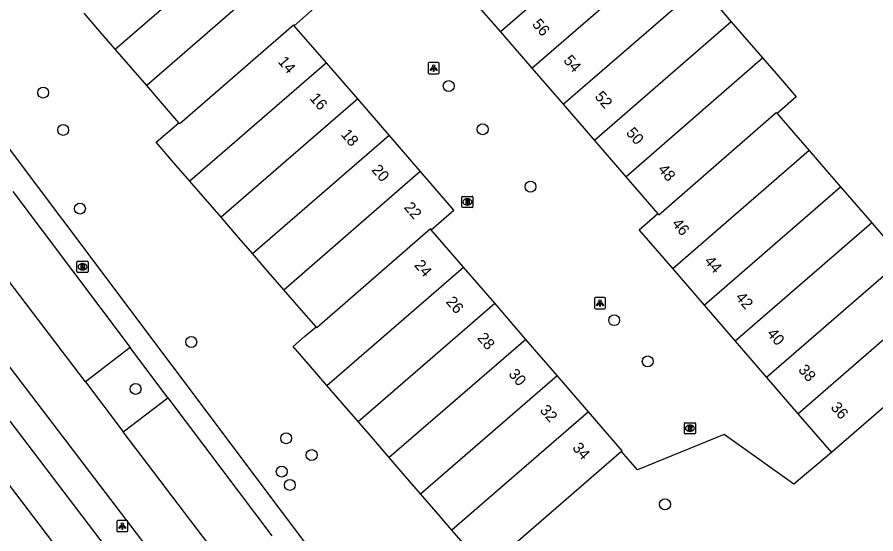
# Model space of a CAD drawing. Extents: x 156664 to 157568, y 383571 to 384421.
# Drawn here: x 156895.5 to 156972.4, y 384208.1 to 384254.3 of the extents above; entities that cross this region are included whole.
import ezdxf

# ---------------------------------------------------------------- set-up
doc = ezdxf.new("R2010")
doc.units = 0
for name, color, linetype in [('IMGEO_Boom', 7, 'Continuous'), ('IMGEO_Brandkraan', 7, 'Continuous'), ('IMGEO_Fietspad_gesloten', 7, 'Continuous'), ('IMGEO_Lichtpunt', 7, 'Continuous'), ('IMGEO_Muur', 7, 'Continuous'), ('IMGEO_Pand', 7, 'Continuous'), ('IMGEO_Pand_nummerreeks', 7, 'Continuous'), ('IMGEO_Parkeervlak_open', 7, 'Continuous'), ('IMGEO_Rijbaan_lokaal_gesloten', 7, 'Continuous'), ('IMGEO_Rioolput', 7, 'Continuous'), ('IMGEO_Voetpad_halfverhard', 7, 'Continuous'), ('IMGEO_Voetpad_open', 7, 'Continuous')]:
    doc.layers.add(name, color=color, linetype=linetype)

msp = doc.modelspace()

# ---------------------------------------------------------------- linework, layer by layer
at = {"layer": 'IMGEO_Boom'}
for centre in [(156934.175, 384248.153), (156897.869, 384247.575), (156899.659, 384244.232), (156937.213, 384244.294), (156941.494, 384239.152), (156901.161, 384237.192), (156948.982, 384227.205), (156911.121, 384225.255), (156951.985, 384223.521), (156906.138, 384221.057), (156919.623, 384216.642), (156921.906, 384215.136), (156919.227, 384213.661), (156919.951, 384212.466), (156953.531, 384210.728)]:
    msp.add_circle(centre, 0.489, dxfattribs=at)
at = {"layer": 'IMGEO_Brandkraan'}
for p, q in [((156935.344, 384237.363), (156935.344, 384238.215)), ((156935.419, 384238.289), (156936.271, 384238.289)), ((156935.832, 384238.069), (156935.857, 384238.069)), ((156936.345, 384238.215), (156936.345, 384237.363)), ((156936.271, 384237.289), (156935.419, 384237.289)), ((156935.855, 384237.509), (156935.83, 384237.509)), ((156900.895, 384231.56), (156900.895, 384232.412)), ((156900.97, 384232.486), (156901.822, 384232.486)), ((156901.383, 384232.266), (156901.408, 384232.266)), ((156901.896, 384232.412), (156901.896, 384231.56)), ((156901.822, 384231.486), (156900.97, 384231.486)), ((156901.406, 384231.706), (156901.381, 384231.706))]:
    msp.add_line(p, q, dxfattribs=at)
for points in [[(156935.344, 384237.363), (156935.344, 384238.215)], [(156935.419, 384238.289), (156936.271, 384238.289)], [(156935.692, 384237.989), (156935.692, 384237.589), (156935.905, 384237.589)], [(156935.923, 384237.989), (156935.692, 384237.989)], [(156935.871, 384237.908), (156935.817, 384237.908), (156935.817, 384237.832)], [(156935.817, 384237.832), (156935.87, 384237.832)], [(156935.879, 384237.756), (156935.817, 384237.756), (156935.817, 384237.675)], [(156935.817, 384237.675), (156935.879, 384237.675)], [(156936.345, 384238.215), (156936.345, 384237.363)], [(156936.271, 384237.289), (156935.419, 384237.289)], [(156900.895, 384231.56), (156900.895, 384232.412)], [(156900.97, 384232.486), (156901.822, 384232.486)], [(156901.243, 384232.186), (156901.243, 384231.786), (156901.456, 384231.786)], [(156901.474, 384232.186), (156901.243, 384232.186)], [(156901.896, 384232.412), (156901.896, 384231.56)], [(156901.822, 384231.486), (156900.97, 384231.486)], [(156901.422, 384232.105), (156901.368, 384232.105), (156901.368, 384232.029)], [(156901.368, 384232.029), (156901.421, 384232.029)], [(156901.43, 384231.953), (156901.368, 384231.953), (156901.368, 384231.872)], [(156901.368, 384231.872), (156901.43, 384231.872)]]:
    msp.add_lwpolyline(points, dxfattribs=at)
for centre, radius, start, end in [((156935.421, 384238.213), 0.0765, 91.55205, 178.44795), ((156935.421, 384238.213), 0.0765, 91.55205, 178.44795), ((156935.872, 384237.87), 0.0379, 267.82845, 90.93552), ((156935.88, 384237.715), 0.0404, 269.87594, 90.50774), ((156935.911, 384237.84), 0.251, 268.66757, 293.53466), ((156935.927, 384237.844), 0.145, 59.4692, 91.53667), ((156935.952, 384237.891), 0.0922, 285.51372, 58.15012), ((156935.957, 384237.699), 0.105, 301.31148, 78.98903), ((156936.269, 384238.213), 0.0765, 1.55205, 88.44795), ((156936.269, 384238.213), 0.0765, 1.55205, 88.44795), ((156935.421, 384237.365), 0.0765, 181.55205, 268.44795), ((156935.421, 384237.365), 0.0765, 181.55205, 268.44795), ((156936.269, 384237.365), 0.0765, 271.55205, 358.44795), ((156936.269, 384237.365), 0.0765, 271.55205, 358.44795), ((156900.972, 384232.41), 0.0765, 91.55205, 178.44795), ((156900.972, 384232.41), 0.0765, 91.55205, 178.44795), ((156901.478, 384232.041), 0.145, 59.4692, 91.53667), ((156901.82, 384232.41), 0.0765, 1.55205, 88.44795), ((156901.82, 384232.41), 0.0765, 1.55205, 88.44795), ((156900.972, 384231.562), 0.0765, 181.55205, 268.44795), ((156900.972, 384231.562), 0.0765, 181.55205, 268.44795), ((156901.423, 384232.067), 0.0379, 267.82845, 90.93552), ((156901.431, 384231.912), 0.0404, 269.87594, 90.50774), ((156901.462, 384232.037), 0.251, 268.66757, 293.53466), ((156901.503, 384232.088), 0.0922, 285.51372, 58.15012), ((156901.508, 384231.896), 0.105, 301.31148, 78.98903), ((156901.82, 384231.562), 0.0765, 271.55205, 358.44795), ((156901.82, 384231.562), 0.0765, 271.55205, 358.44795)]:
    msp.add_arc(centre, radius, start, end, dxfattribs=at)
for centre, major_axis, ratio, start_param, end_param in [((156935.831, 384237.789), (-0.387, 0.002), 0.722429, 4.712389, 7.853982), ((156935.856, 384237.789), (-0.39, 0.002), 0.717154, 1.570796, 4.712389), ((156901.382, 384231.986), (-0.387, 0.002), 0.722429, 4.712389, 7.853982), ((156901.407, 384231.986), (-0.39, 0.002), 0.717154, 1.570796, 4.712389)]:
    msp.add_ellipse(centre, major_axis=major_axis, ratio=ratio, start_param=start_param, end_param=end_param, dxfattribs=at)
at = {"layer": 'IMGEO_Fietspad_gesloten'}
for points in [[(156849.254, 384272.327), (156925.032, 384172.754), (156949.045, 384141.371)], [(156945.927, 384151.336), (156927.81, 384174.952), (156867.867, 384253.653)]]:
    msp.add_lwpolyline(points, dxfattribs=at)
at = {"layer": 'IMGEO_Lichtpunt'}
for p, q in [((156932.325, 384250.162), (156932.325, 384249.355)), ((156932.325, 384250.162), (156932.325, 384249.355)), ((156933.227, 384250.257), (156932.419, 384250.257)), ((156933.227, 384250.257), (156932.419, 384250.257)), ((156933.321, 384249.355), (156933.321, 384250.162)), ((156933.321, 384249.355), (156933.321, 384250.162)), ((156932.419, 384249.261), (156933.227, 384249.261)), ((156932.419, 384249.261), (156933.227, 384249.261)), ((156947.218, 384229.131), (156947.218, 384228.324)), ((156947.218, 384229.131), (156947.218, 384228.324)), ((156948.12, 384229.226), (156947.312, 384229.226)), ((156948.12, 384229.226), (156947.312, 384229.226)), ((156948.214, 384228.324), (156948.214, 384229.131)), ((156948.214, 384228.324), (156948.214, 384229.131)), ((156947.312, 384228.23), (156948.12, 384228.23)), ((156947.312, 384228.23), (156948.12, 384228.23)), ((156904.455, 384209.184), (156904.455, 384208.377)), ((156904.455, 384209.184), (156904.455, 384208.377)), ((156905.357, 384209.279), (156904.549, 384209.279)), ((156905.357, 384209.279), (156904.549, 384209.279)), ((156905.451, 384208.377), (156905.451, 384209.184)), ((156905.451, 384208.377), (156905.451, 384209.184)), ((156904.549, 384208.283), (156905.357, 384208.283)), ((156904.549, 384208.283), (156905.357, 384208.283))]:
    msp.add_line(p, q, dxfattribs=at)
for points in [[(156932.699, 384249.826), (156932.738, 384249.798), (156932.55, 384249.536), (156932.512, 384249.563), (156932.699, 384249.826)], [(156932.801, 384249.778), (156932.848, 384249.778), (156932.848, 384249.456), (156932.801, 384249.456), (156932.801, 384249.778)], [(156932.911, 384249.798), (156932.949, 384249.825), (156933.136, 384249.563), (156933.097, 384249.535), (156932.911, 384249.798)], [(156947.592, 384228.795), (156947.631, 384228.767), (156947.443, 384228.505), (156947.405, 384228.532), (156947.592, 384228.795)], [(156947.694, 384228.747), (156947.741, 384228.747), (156947.741, 384228.425), (156947.694, 384228.425), (156947.694, 384228.747)], [(156947.804, 384228.767), (156947.842, 384228.794), (156948.029, 384228.532), (156947.99, 384228.504), (156947.804, 384228.767)], [(156904.829, 384208.848), (156904.868, 384208.82), (156904.68, 384208.558), (156904.642, 384208.585), (156904.829, 384208.848)], [(156904.931, 384208.8), (156904.978, 384208.8), (156904.978, 384208.478), (156904.931, 384208.478), (156904.931, 384208.8)], [(156905.041, 384208.82), (156905.079, 384208.847), (156905.266, 384208.585), (156905.227, 384208.557), (156905.041, 384208.82)]]:
    msp.add_lwpolyline(points, dxfattribs=at)
for centre in [(156932.824, 384249.96), (156947.717, 384228.929), (156904.954, 384208.982)]:
    msp.add_circle(centre, 0.0994, dxfattribs=at)
for centre, start, end in [((156932.419, 384250.162), 90, 180), ((156932.419, 384250.162), 90, 180), ((156933.227, 384250.162), 0, 90), ((156933.227, 384250.162), 0, 90), ((156932.419, 384249.355), 180, 270), ((156932.419, 384249.355), 180, 270), ((156933.227, 384249.355), 270, 0), ((156933.227, 384249.355), 270, 360), ((156947.312, 384229.131), 90, 180), ((156947.312, 384229.131), 90, 180), ((156948.12, 384229.131), 0, 90), ((156948.12, 384229.131), 0, 90), ((156947.312, 384228.324), 180, 270), ((156947.312, 384228.324), 180, 270), ((156948.12, 384228.324), 270, 0), ((156948.12, 384228.324), 270, 360), ((156904.549, 384209.184), 90, 180), ((156904.549, 384209.184), 90, 180), ((156905.357, 384209.184), 0, 90), ((156905.357, 384209.184), 0, 90), ((156904.549, 384208.377), 180, 270), ((156904.549, 384208.377), 180, 270), ((156905.357, 384208.377), 270, 0), ((156905.357, 384208.377), 270, 360)]:
    msp.add_arc(centre, 0.0946, start, end, dxfattribs=at)
at = {"layer": 'IMGEO_Muur'}
msp.add_lwpolyline([(156968.443, 384215.362), (156965.076, 384212.541), (156958.843, 384216.97), (156951.07, 384213.826), (156949.633, 384215.464)], dxfattribs=at)
at = {"layer": 'IMGEO_Pand'}
for points in [[(156951.063, 384263.597), (156938.813, 384253.005)], [(156904.328, 384251.453), (156916.555, 384262.053)], [(156941.619, 384249.764), (156953.864, 384260.365)], [(156919.359, 384258.813), (156907.137, 384248.212)], [(156920.35, 384253.561), (156922.366, 384255.339), (156919.359, 384258.813)], [(156944.424, 384246.522), (156956.664, 384257.133)], [(156956.664, 384257.133), (156958.073, 384255.507), (156959.465, 384253.901)], [(156936.014, 384256.239), (156938.813, 384253.005)], [(156904.328, 384251.453), (156902.944, 384253.05), (156901.526, 384254.688)], [(156959.465, 384253.901), (156947.224, 384243.288)], [(156959.465, 384253.901), (156960.852, 384252.3), (156962.265, 384250.669)], [(156910.024, 384244.879), (156910.089, 384244.803), (156920.285, 384253.637), (156920.35, 384253.561)], [(156923.227, 384250.237), (156920.35, 384253.561)], [(156938.813, 384253.005), (156941.619, 384249.764)], [(156907.137, 384248.212), (156905.709, 384249.86), (156904.328, 384251.453)], [(156950.03, 384240.046), (156962.265, 384250.669)], [(156962.265, 384250.669), (156963.682, 384249.034), (156965.282, 384247.188), (156963.566, 384245.705)], [(156923.227, 384250.237), (156910.997, 384239.653)], [(156926.025, 384247.004), (156923.227, 384250.237)], [(156941.619, 384249.764), (156944.424, 384246.522)], [(156910.024, 384244.879), (156908.56, 384246.569), (156907.137, 384248.212)], [(156926.025, 384247.004), (156913.799, 384236.419)], [(156928.83, 384243.763), (156926.025, 384247.004)], [(156944.424, 384246.522), (156947.224, 384243.288)], [(156952.901, 384236.729), (156952.972, 384236.646), (156963.494, 384245.788), (156963.566, 384245.705)], [(156963.566, 384245.705), (156965.048, 384243.993), (156966.445, 384242.38)], [(156910.997, 384239.653), (156909.575, 384241.293), (156907.985, 384243.129), (156910.024, 384244.879)], [(156916.608, 384233.177), (156928.83, 384243.763)], [(156931.629, 384240.53), (156928.83, 384243.763)], [(156947.224, 384243.288), (156950.03, 384240.046)], [(156966.445, 384242.38), (156954.226, 384231.79)], [(156966.445, 384242.38), (156967.882, 384240.721), (156969.253, 384239.138)], [(156919.417, 384229.935), (156931.629, 384240.53)], [(156932.609, 384235.287), (156934.643, 384237.047), (156931.629, 384240.53)], [(156950.03, 384240.046), (156952.901, 384236.729)], [(156913.799, 384236.419), (156912.406, 384238.026), (156910.997, 384239.653)], [(156957.025, 384228.555), (156969.253, 384239.138)], [(156969.253, 384239.138), (156970.649, 384237.525), (156972.054, 384235.903)], [(156916.608, 384233.177), (156915.177, 384234.828), (156913.799, 384236.419)], [(156952.901, 384236.729), (156951.211, 384235.273), (156954.226, 384231.79)], [(156932.609, 384235.287), (156932.537, 384235.37), (156922.363, 384226.534), (156922.298, 384226.61)], [(156935.487, 384231.961), (156932.609, 384235.287)], [(156972.054, 384235.903), (156959.824, 384225.321)], [(156972.054, 384235.903), (156973.463, 384234.275), (156974.854, 384232.669)], [(156919.417, 384229.935), (156918.022, 384231.544), (156916.608, 384233.177)], [(156974.854, 384232.669), (156962.629, 384222.08)], [(156923.257, 384221.376), (156935.487, 384231.961)], [(156938.286, 384228.726), (156935.487, 384231.961)], [(156954.226, 384231.79), (156957.025, 384228.555)], [(156922.298, 384226.61), (156920.796, 384228.343), (156919.417, 384229.935)], [(156965.435, 384218.838), (156977.655, 384229.434)], [(156977.655, 384229.434), (156979.069, 384227.802), (156980.672, 384225.95), (156968.443, 384215.362)], [(156926.055, 384218.142), (156938.286, 384228.726)], [(156941.086, 384225.491), (156938.286, 384228.726)], [(156957.025, 384228.555), (156959.824, 384225.321)], [(156923.257, 384221.376), (156921.821, 384223.035), (156920.243, 384224.86), (156921.276, 384225.74), (156922.298, 384226.61)], [(156941.086, 384225.491), (156928.853, 384214.907)], [(156943.893, 384222.249), (156941.086, 384225.491)], [(156959.824, 384225.321), (156962.629, 384222.08)], [(156931.658, 384211.665), (156943.893, 384222.249)], [(156946.692, 384219.014), (156943.893, 384222.249)], [(156962.629, 384222.08), (156965.435, 384218.838)], [(156926.055, 384218.142), (156924.641, 384219.776), (156923.257, 384221.376)], [(156946.692, 384219.014), (156934.463, 384208.423)], [(156949.633, 384215.464), (156949.708, 384215.53), (156946.692, 384219.014)], [(156965.435, 384218.838), (156968.443, 384215.362)], [(156928.853, 384214.907), (156927.432, 384216.55), (156926.055, 384218.142)], [(156949.633, 384215.464), (156937.483, 384204.932), (156935.882, 384206.783), (156934.463, 384208.423)], [(156931.658, 384211.665), (156930.276, 384213.263), (156928.853, 384214.907)], [(156934.463, 384208.423), (156933.038, 384210.07), (156931.658, 384211.665)]]:
    msp.add_lwpolyline(points, dxfattribs=at)
at = {"layer": 'IMGEO_Parkeervlak_open'}
for points in [[(156905.644, 384224.752), (156901.645, 384221.683)], [(156905.044, 384217.212), (156909.04, 384220.251)]]:
    msp.add_lwpolyline(points, dxfattribs=at)
at = {"layer": 'IMGEO_Rijbaan_lokaal_gesloten'}
for points in [[(156869.636, 384256.091), (156947.883, 384153.474), (156948.198, 384153.058)], [(156901.645, 384221.683), (156891.001, 384235.643)], [(156901.645, 384221.683), (156905.044, 384217.212)], [(156914.397, 384204.906), (156905.044, 384217.212)]]:
    msp.add_lwpolyline(points, dxfattribs=at)
at = {"layer": 'IMGEO_Rioolput'}
for p, q in [((156955.264, 384217.108), (156955.264, 384217.96)), ((156955.339, 384218.034), (156956.191, 384218.034)), ((156955.752, 384217.814), (156955.777, 384217.814)), ((156956.265, 384217.96), (156956.265, 384217.108)), ((156956.191, 384217.034), (156955.339, 384217.034)), ((156955.775, 384217.254), (156955.75, 384217.254))]:
    msp.add_line(p, q, dxfattribs=at)
for points in [[(156955.264, 384217.108), (156955.264, 384217.96)], [(156955.339, 384218.034), (156956.191, 384218.034)], [(156955.853, 384217.732), (156955.601, 384217.734), (156955.601, 384217.334)], [(156955.779, 384217.653), (156955.725, 384217.653), (156955.725, 384217.572)], [(156956.265, 384217.96), (156956.265, 384217.108)], [(156956.191, 384217.034), (156955.339, 384217.034)], [(156955.601, 384217.334), (156955.725, 384217.334), (156955.725, 384217.496), (156955.736, 384217.496)], [(156955.725, 384217.572), (156955.777, 384217.572)], [(156955.783, 384217.467), (156955.854, 384217.334), (156955.994, 384217.334), (156955.929, 384217.46)]]:
    msp.add_lwpolyline(points, dxfattribs=at)
for centre, radius, start, end in [((156955.341, 384217.958), 0.0765, 91.55205, 178.44795), ((156955.341, 384217.958), 0.0765, 91.55205, 178.44795), ((156955.785, 384217.557), 0.0964, 77.00612, 93.18647), ((156955.799, 384217.614), 0.0378, 276.66336, 79.67722), ((156955.852, 384217.622), 0.109, 350.36119, 89.41601), ((156955.85, 384217.622), 0.112, 277.58423, 350.98172), ((156956.189, 384217.958), 0.0765, 1.55205, 88.44795), ((156956.189, 384217.958), 0.0765, 1.55205, 88.44795), ((156955.341, 384217.11), 0.0765, 181.55205, 268.44795), ((156955.341, 384217.11), 0.0765, 181.55205, 268.44795), ((156955.735, 384217.443), 0.0533, 26.02933, 88.69889), ((156955.761, 384217.761), 0.19, 274.7715, 282.96867), ((156955.834, 384217.407), 0.108, 29.51342, 73.79051), ((156956.189, 384217.11), 0.0765, 271.55205, 358.44795), ((156956.189, 384217.11), 0.0765, 271.55205, 358.44795)]:
    msp.add_arc(centre, radius, start, end, dxfattribs=at)
for centre, major_axis, ratio, start_param, end_param in [((156955.751, 384217.534), (-0.387, 0.002), 0.722429, 4.712389, 7.853982), ((156955.776, 384217.534), (-0.39, 0.002), 0.717154, 1.570796, 4.712389)]:
    msp.add_ellipse(centre, major_axis=major_axis, ratio=ratio, start_param=start_param, end_param=end_param, dxfattribs=at)
at = {"layer": 'IMGEO_Voetpad_halfverhard'}
msp.add_lwpolyline([(156968.443, 384215.362), (156965.076, 384212.541), (156958.843, 384216.97), (156951.07, 384213.826), (156949.633, 384215.464)], dxfattribs=at)
at = {"layer": 'IMGEO_Voetpad_open'}
for points in [[(156879.806, 384262.53), (156939.02, 384183.696), (156943.34, 384177.955), (156946.64, 384173.562), (156953.814, 384164.012), (156954.003, 384163.76)], [(156895.163, 384238.727), (156905.644, 384224.752)], [(156909.04, 384220.251), (156905.644, 384224.752)], [(156909.04, 384220.251), (156918.348, 384207.896)]]:
    msp.add_lwpolyline(points, dxfattribs=at)

# ---------------------------------------------------------------- texts
at = {"layer": 'IMGEO_Pand_nummerreeks'}
for s, rotation, p in [('56', 310.87649, (156941.582, 384253.656)), ('14', 310.87775, (156918.829, 384250.306)), ('54', 310.87649, (156944.388, 384250.415)), ('52', 310.87649, (156947.186, 384247.182)), ('16', 310.87775, (156921.667, 384247.027)), ('50', 310.87649, (156949.995, 384243.936)), ('18', 310.87775, (156924.47, 384243.788)), ('20', 310.87775, (156927.213, 384240.62)), ('48', 310.87649, (156952.834, 384240.657)), ('22', 310.87775, (156930.113, 384237.269)), ('46', 310.87412, (156954.085, 384235.803)), ('24', 310.87625, (156931.029, 384232.1)), ('44', 310.87412, (156956.992, 384232.444)), ('26', 310.87625, (156933.868, 384228.82)), ('42', 310.87412, (156959.787, 384229.215)), ('28', 310.87625, (156936.669, 384225.583)), ('40', 310.87412, (156962.595, 384225.97)), ('38', 310.87412, (156965.401, 384222.728)), ('30', 310.87625, (156939.473, 384222.344)), ('36', 310.87412, (156968.305, 384219.372)), ('32', 310.87625, (156942.269, 384219.113)), ('34', 310.87625, (156945.181, 384215.748))]:
    msp.add_text(s, height=1, rotation=rotation, dxfattribs=at).set_placement(p)

doc.saveas('drawing.dxf')
